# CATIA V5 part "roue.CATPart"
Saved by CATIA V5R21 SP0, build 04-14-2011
Part number: roue
Revision: A
Nomenclature: 3
Material "Aluminium": density 2710 kg/m3, Young's modulus 7e+10 Pa, Poisson ratio 0.346, thermal expansion 2.36e-05 1/K
Bounding box of the stored display mesh (mm): x -36.5 to 20, y -31 to 31, z -31 to 31
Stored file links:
  C:\Users\Olivier\Desktop\redaction CATIA (local)\CATIA\DONNEES\Exercice mise en plan 2 (Pompe de ventilation)\Pompe de ventilation (Product inclus)\roue.CATPart
  C:\Program Files\Dassault Systemes\B21\win_b64\startup\materials\French\Catalog.CATMaterial
  C:\Users\Olivier\Desktop\redaction CATIA (local)\CATIA\DONNEES\Exercice mise en plan 2 (Pompe de ventilation)\Pompe de ventilation (Product inclus)\CATIA_EnvironmentMap_Satin_512x512.jpg
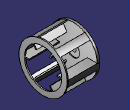
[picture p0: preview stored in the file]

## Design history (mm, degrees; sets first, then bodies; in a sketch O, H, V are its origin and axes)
Body1 (main body), material "Aluminium"
  Sketch1 on yz-plane, origin (0, 0, 0), H (0, 1, 0), V (0, 0, 1)
    arc A1 centre (0, 0) radius 31 from (21.7261, 22.1128) to (14.8459, 27.2139) ccw
    arc A2 centre (0, 0) radius 29.5 from (20.6749, 21.0428) to (15.3948, 25.1645) ccw
    line L1 (9.6319, 15.1829) -> (15.3948, 25.1645)
    line L2 (8.3328, 15.9329) -> (14.8459, 27.2139)
    construction line L3 (0, 0) -> (-1.299, 0.75)
    line L4 (20.6749, 21.0428) -> (21.7261, 22.1128)
    arc A3 centre (0, 0) radius 17.9804 from (9.6319, 15.1829) to (8.3328, 15.9329) ccw
    angle L1 H = 60
    distance L1 L2 = 1.5
    distance A1 A2 = 1.5
    radius A1 = 31
    perpendicularity: L3 L1, L3 L2
  Pad1: profile Sketch1, direction (1, 0, 0), length 20, mirrored extent
  Sketch2 on start face of Pad1, origin (-20, 0, 0), H (0, -1, 0), V (0, 0, 1)
    reference projected arc E1 centre (0, 0) radius 31 from (-14.8459, 27.2139) to (-21.7261, 22.1128) ccw from edge [start face of Pad1 | face of Pad1 from Sketch1.A1]
    circle A1 centre (0, 0) radius 31
    point P3 (-17.8616, 25.337)
    circle A2 centre (0, 0) radius 2.5
    circle A3 centre (0, 0) radius 8
    radius A2 = 2.5
    radius A3 = 8
    coincidence: A1 P3, P3 E1
  Sketch3 on end face of Pad1, origin (20, 0, 0), H (0, 1, 0), V (0, 0, 1)
    circle A1 centre (0, 0) radius 24
    circle A2 centre (0, 0) radius 31
    radius A1 = 24
    radius A2 = 31
  Pad2: profile Sketch3, direction (-1, 0, 0), length 1.5
  MultiPad1: profile Sketch2, domains (length 16.5; length 0; length 2 / length 1)
  Sketch4 on face of MultiPad1, origin (-36.5, 0, 0), H (0, -1, 0), V (0, 0, 1)
    circle A1 centre (0, 0) radius 4.5
  Pocket1: profile Sketch4, direction (1, 0, 0), length 12
  CircPattern1: of Pad1, instances 6, angular step 60, axis from end face of Pad2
